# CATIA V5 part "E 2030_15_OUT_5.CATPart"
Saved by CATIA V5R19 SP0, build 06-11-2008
Material "Plastic": density 1200 kg/m3, Young's modulus 2.2e+09 Pa, Poisson ratio 0.38, thermal expansion 6.84e-05 1/K
Bounding box of the stored display mesh (mm): x -7.55 to 7.55, y -30.19 to -15.11, z -2 to 0
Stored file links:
  G:\UTB\Kombinované\Bakalářská práce\Catia\FORMA\E 2030_15_OUT_5.CATPart
  D:\Aplikace\CATIA\Nová složka\win_b64\startup\materials\Catalog.CATMaterial
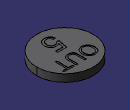
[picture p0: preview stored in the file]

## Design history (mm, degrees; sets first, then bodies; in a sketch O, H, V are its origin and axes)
Body1 "E 2030_15_OUT_1-8" (main body)
  Solid1: solid without history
